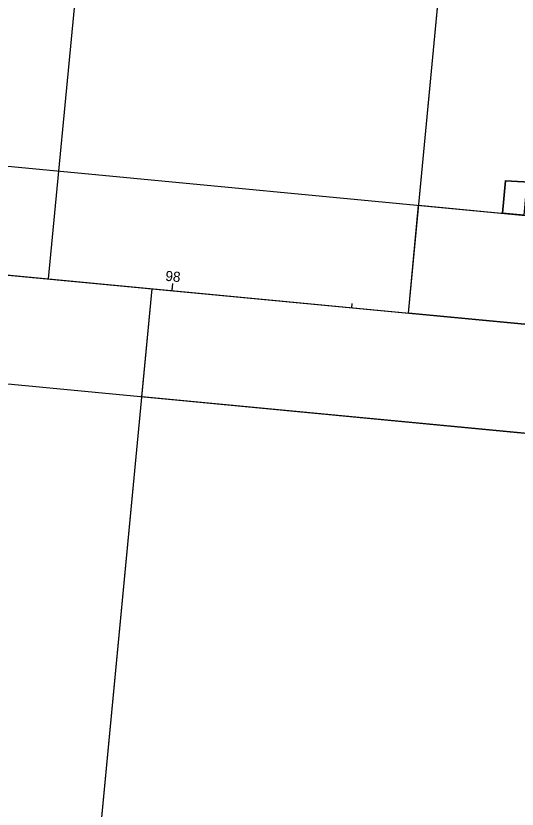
# Model space of a CAD drawing. Extents: x 2318731 to 2320621, y 732958 to 734198.
# Drawn here: x 2319093.1 to 2319231.8, y 733409.1 to 733628.7 of the extents above; entities that cross this region are included whole.
import ezdxf

# ---------------------------------------------------------------- set-up
doc = ezdxf.new("R2010")
doc.units = 0
for name, color, linetype in [('RW_P_Easement_Area', 7, 'Continuous'), ('RW_P_Esmt_TMP', 7, 'Continuous'), ('RW_X_CL_100_Stations', 7, 'Continuous'), ('RW_X_CL_500_Stations', 7, 'Continuous'), ('SC_Scratch3', 7, 'Continuous'), ('SC_Scratch4', 7, 'Continuous'), ('SC_Scratch5', 7, 'Continuous'), ('SV_P_Control_Cells_Set', 7, 'Continuous'), ('V-SURV-IPF', 7, 'Continuous'), ('V-SURV-PARL-LINE', 7, 'Continuous'), ('V-SURV-RWAY', 7, 'Continuous')]:
    doc.layers.add(name, color=color, linetype=linetype)

msp = doc.modelspace()

# ---------------------------------------------------------------- linework, layer by layer
at = {"layer": 'RW_P_Easement_Area'}
for p, q in [((2319227.77, 733574.05), (2319228.62, 733583.01)), ((2319228.62, 733583.01), (2319317.64, 733578.16)), ((2319233.74, 733573.49), (2319227.77, 733574.05))]:
    msp.add_line(p, q, dxfattribs=at)
at = {"layer": 'RW_P_Esmt_TMP'}
for p, q in [((2319227.77, 733574.05), (2319228.62, 733583.02)), ((2319228.62, 733583.02), (2319317.64, 733578.16))]:
    msp.add_line(p, q, dxfattribs=at)
at = {"layer": 'RW_X_CL_100_Stations'}
for p, q in [((2319136.33, 733552.62), (2319136.52, 733554.61)), ((2319186.1, 733547.89), (2319186.22, 733549.08))]:
    msp.add_line(p, q, dxfattribs=at)
at = {"layer": 'RW_X_CL_500_Stations'}
msp.add_line((2319136.33, 733552.62), (2319136.44, 733553.82), dxfattribs=at)
at = {"layer": 'SC_Scratch3'}
msp.add_lwpolyline([(2319228.62, 733583.02), (2319227.77, 733574.05), (2319233.75, 733573.49), (2319234.34, 733579.7), (2319317.45, 733574.31), (2319317.21, 733569.31), (2319387.15, 733565.99), (2319317.63, 733578.16)], close=True, dxfattribs=at)
at = {"layer": 'SC_Scratch4'}
for points in [[(2319238.01, 733573.08), (2319387.15, 733565.99), (2319438.37, 733857.2), (2319458.71, 733857.41), (2319402.05, 733535.25), (2319235.88, 733543.15), (2319201.73, 733546.4), (2319204.58, 733576.26)], [(2319235.88, 733543.15), (2319303.98, 733539.91), (2319302.56, 733509.94), (2319233.74, 733513.21), (2319127.98, 733523.28), (2319130.82, 733553.15)]]:
    msp.add_lwpolyline(points, close=True, dxfattribs=at)
msp.add_lwpolyline([(2318852.08, 733579.68), (2319235.88, 733543.15), (2319306.05, 733539.81)], dxfattribs=at)
at = {"layer": 'SC_Scratch5'}
for points in [[(2319402.05, 733535.25), (2319235.88, 733543.15), (2319201.73, 733546.4), (2319231.12, 733855.03), (2319458.71, 733857.41)], [(2319235.88, 733543.15), (2319303.98, 733539.91), (2319288.31, 733210.28), (2319212.39, 733213.89), (2319099.55, 733224.63), (2319130.82, 733553.15)]]:
    msp.add_lwpolyline(points, close=True, dxfattribs=at)
at = {"layer": 'SV_P_Control_Cells_Set'}
for p, q in [((2319228.58, 733583.02), (2319228.67, 733583.01)), ((2319228.62, 733582.97), (2319228.63, 733583.06)), ((2319227.72, 733574.06), (2319227.82, 733574.05)), ((2319227.77, 733574.01), (2319227.78, 733574.1))]:
    msp.add_line(p, q, dxfattribs=at)
at = {"layer": 'V-SURV-IPF'}
for p, q in [((2319102.18, 733555.87), (2319130.56, 733853.98)), ((2319201.73, 733546.4), (2319231.13, 733855.14)), ((2319099.55, 733224.63), (2319130.82, 733553.15))]:
    msp.add_line(p, q, dxfattribs=at)
at = {"layer": 'V-SURV-PARL-LINE'}
for p, q in [((2318854.93, 733609.55), (2319237.97, 733573.08)), ((2318879.11, 733546.98), (2319233.74, 733513.21))]:
    msp.add_line(p, q, dxfattribs=at)
at = {"layer": 'V-SURV-RWAY'}
msp.add_line((2318852.08, 733579.68), (2319235.88, 733543.15), dxfattribs=at)

# ---------------------------------------------------------------- texts
at = {"layer": 'RW_X_CL_100_Stations'}
msp.add_text('98', height=2.8, rotation=354.5618, dxfattribs=at).set_placement((2319134.39, 733555.37))

doc.saveas('drawing.dxf')
